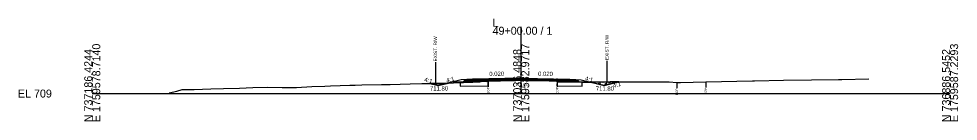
# Model space of a CAD drawing. Extents: x -26 to 4303, y -10 to 9577.
# Drawn here: x 2974.3 to 3302.8, y 8990.3 to 9026.2 of the extents above; entities that cross this region are included whole.
import ezdxf

# ---------------------------------------------------------------- set-up
doc = ezdxf.new("R2010")
doc.units = 0
for name, color, linetype in [('Default', 7, 'Continuous'), ('Exist CMT Pavement', 7, 'Continuous'), ('Old_Level_2', 7, 'Continuous'), ('Pattern 3', 7, 'Continuous'), ('Prop CMT Conc Surface', 7, 'Continuous'), ('Prop CMT Concrete Structures', 7, 'Continuous'), ('Prop CMT Pvmt Course 1', 7, 'Continuous'), ('Prop CMT Pvmt Course 1 CG', 7, 'Continuous'), ('Prop CMT Pvmt Course 1 Wedge', 7, 'Continuous'), ('Prop CMT Pvmt Course 2', 7, 'Continuous'), ('Prop CMT Pvmt Course 2 Wedge', 7, 'Continuous'), ('Prop CMT Pvmt Course 3', 7, 'Continuous'), ('Prop CMT Pvmt Surface', 7, 'Continuous'), ('Prop CMT Pvmt Surface Shoulder', 7, 'Continuous'), ('Prop CMT Pvmt Wedge Surface 1', 7, 'Continuous'), ('Prop CMT Pvmt Wedge Surface 2', 7, 'Continuous'), ('Prop CMT Pvmt Wedge Surface 3', 7, 'Continuous'), ('Prop CMT Shld Paved Course 1', 7, 'Continuous'), ('Prop CMT Shld Paved Course 2', 7, 'Continuous'), ('Prop CMT Shld Paved Course 3', 7, 'Continuous'), ('Prop CMT Slope Grass', 7, 'Continuous'), ('Prop CMT Subgrade Earthwork', 7, 'Continuous'), ('Prop Road Sect_ Recs - UC Shallow (Outline)', 7, 'Continuous'), ('Prop Shade Light', 7, 'Continuous'), ('Prop XS DDE Elevations', 7, 'Continuous'), ('Prop XS Ditch Standard Text', 7, 'Continuous'), ('Prop XS Hydro Elevations', 7, 'Continuous'), ('Prop XS SE Text', 7, 'Continuous'), ('Prop XS Side Slope Text', 7, 'Continuous'), ('Prop XS Wedging', 7, 'Continuous'), ('Scratch_Level_2', 7, 'Continuous')]:
    doc.layers.add(name, color=color, linetype=linetype)

msp = doc.modelspace()

# ---------------------------------------------------------------- linework, layer by layer
at = {"layer": 'Exist CMT Pavement'}
for points in [[(3150, 9005.34), (3133, 9005)], [(3150, 9005.34), (3167, 9005)]]:
    msp.add_lwpolyline(points, dxfattribs=at)
at = {"layer": 'Old_Level_2'}
for p, q in [((3150, 9000), (3150, 9023.41)), ((3150, 9000), (3150, 9023.41)), ((3000, 9000), (3150, 9000)), ((3000, 9000), (3150, 9000)), ((3150, 9000), (3300, 9000)), ((3150, 9000), (3300, 9000))]:
    msp.add_line(p, q, dxfattribs=at)
at = {"layer": 'Pattern 3'}
for p, q in [((3118.62, 9003.55), (3118.58, 9003.43)), ((3119.54, 9003.23), (3119.63, 9003.14)), ((3120.15, 9003.4), (3120.05, 9003.04)), ((3120.49, 9002.93), (3120.59, 9002.95)), ((3121.01, 9003.56), (3120.94, 9003.31)), ((3121.45, 9003.56), (3121.54, 9003.47)), ((3121.9, 9003.12), (3121.97, 9003.04)), ((3122.5, 9003.28), (3122.47, 9003.17)), ((3123.42, 9003.64), (3123.35, 9003.39)), ((3123.6, 9003.65), (3123.76, 9003.49)), ((3175.15, 9003.96), (3175.1, 9003.78)), ((3176, 9004.06), (3175.95, 9003.87)), ((3176.52, 9004.06), (3176.55, 9004.03)), ((3176.91, 9003.68), (3177.38, 9003.21)), ((3177.3, 9003.23), (3177.95, 9003.4)), ((3177.51, 9003.84), (3177.34, 9003.22)), ((3178.39, 9004.07), (3178.31, 9003.75)), ((3178.75, 9004.07), (3178.91, 9003.92)), ((3179.1, 9002.96), (3180.31, 9003.28)), ((3179.26, 9003.56), (3179.82, 9003.01)), ((3179.87, 9003.72), (3179.66, 9002.97)), ((3180.22, 9004.08), (3180.24, 9004.08)), ((3180.78, 9004.09), (3180.66, 9003.64)), ((3180.98, 9004.09), (3181.27, 9003.8)), ((3182.58, 9003.96), (3183.09, 9004.1)), ((3183.17, 9004.1), (3183.1, 9003.83)), ((3183.2, 9004.1), (3183.4, 9003.9))]:
    msp.add_line(p, q, dxfattribs=at)
for points in [[(3118.04, 9003.54), (3121, 9002.8), (3124.57, 9003.7), (3124.11, 9003.68), (3121.85, 9003.57)], [(3135.79, 9004.18), (3136.61, 9004.36), (3137.39, 9004.36), (3137.86, 9004.22)], [(3137.9, 9004.23), (3138.46, 9004.36), (3138.45, 9004.24)], [(3162.55, 9004.39), (3162.55, 9004.22), (3170.16, 9004.06)], [(3184.18, 9004.1), (3179, 9002.8), (3174.01, 9004.05), (3181.14, 9004.09), (3181.96, 9004.1)]]:
    msp.add_lwpolyline(points, close=True, dxfattribs=at)
at = {"layer": 'Prop CMT Conc Surface'}
for points in [[(3138.45, 9004.86), (3133, 9004.75)], [(3133, 9004.75), (3133, 9004.54)], [(3133, 9004.54), (3138.45, 9004.65)], [(3138.45, 9004.65), (3138.45, 9004.86)], [(3162.55, 9004.63), (3162.55, 9004.84)], [(3162.55, 9004.84), (3167, 9004.75)], [(3167, 9004.54), (3162.55, 9004.63)], [(3167, 9004.75), (3167, 9004.54)]]:
    msp.add_lwpolyline(points, dxfattribs=at)
at = {"layer": 'Prop CMT Concrete Structures'}
for points in [[(3150, 9005.22), (3138.45, 9004.99)], [(3150, 9005.22), (3162.55, 9004.97)], [(3133, 9004.75), (3133, 9005)], [(3138.45, 9004.86), (3133, 9004.75)], [(3138.45, 9004.99), (3138.45, 9004.86)], [(3162.55, 9004.97), (3162.55, 9004.84)], [(3162.55, 9004.84), (3167, 9004.75)], [(3167, 9004.75), (3167, 9005)]]:
    msp.add_lwpolyline(points, dxfattribs=at)
at = {"layer": 'Prop CMT Pvmt Course 1'}
for points in [[(3138.45, 9004.65), (3133, 9004.54)], [(3133, 9004.54), (3133, 9004.21)], [(3133, 9004.21), (3138.45, 9004.32)], [(3138.45, 9004.32), (3138.45, 9004.65)], [(3162.55, 9004.63), (3167, 9004.54)], [(3162.55, 9004.3), (3162.55, 9004.63)], [(3167, 9004.21), (3162.55, 9004.3)], [(3167, 9004.54), (3167, 9004.21)]]:
    msp.add_lwpolyline(points, dxfattribs=at)
at = {"layer": 'Prop CMT Pvmt Course 1 Wedge'}
for points in [[(3138.45, 9004.65), (3138.66, 9004.66), (3139.05, 9004.67), (3139.08, 9004.67), (3139.28, 9004.67), (3139.53, 9004.67), (3140.23, 9004.69), (3141.26, 9004.71), (3142.73, 9004.74), (3143.69, 9004.76), (3145.23, 9004.79), (3146.12, 9004.81), (3147.73, 9004.84), (3148.16, 9004.85), (3149.92, 9004.88), (3150, 9004.88)], [(3150, 9004.65), (3149.92, 9004.65), (3148.16, 9004.63), (3147.73, 9004.63), (3146.12, 9004.62), (3145.23, 9004.62), (3143.69, 9004.56), (3142.73, 9004.52), (3141.26, 9004.5), (3140.23, 9004.48), (3139.53, 9004.46), (3139.28, 9004.45), (3139.08, 9004.45), (3139.05, 9004.44), (3138.66, 9004.41), (3138.45, 9004.36)], [(3138.45, 9004.36), (3138.45, 9004.65)], [(3150, 9004.88), (3150, 9004.65)], [(3150, 9004.88), (3151.47, 9004.85), (3152.03, 9004.84), (3152.74, 9004.83), (3153.42, 9004.82), (3155.24, 9004.78), (3155.85, 9004.77), (3157.74, 9004.73), (3159.74, 9004.69), (3160.24, 9004.68), (3160.51, 9004.67), (3160.64, 9004.67), (3160.96, 9004.66), (3161.66, 9004.65), (3162.35, 9004.64), (3162.55, 9004.63)], [(3162.55, 9004.39), (3162.35, 9004.4), (3161.66, 9004.44), (3160.96, 9004.47), (3160.64, 9004.48), (3160.51, 9004.48), (3160.24, 9004.5), (3159.74, 9004.51), (3157.74, 9004.53), (3155.85, 9004.59), (3155.24, 9004.61), (3153.42, 9004.61), (3152.74, 9004.61), (3152.03, 9004.61), (3151.47, 9004.63), (3150, 9004.65)], [(3162.55, 9004.63), (3162.55, 9004.39)]]:
    msp.add_lwpolyline(points, dxfattribs=at)
at = {"layer": 'Prop CMT Pvmt Course 2'}
for points in [[(3133, 9005), (3131, 9004.96), (3130.74, 9004.71)], [(3130.74, 9004.71), (3133, 9004.75)], [(3133, 9004.75), (3133, 9005)], [(3167, 9005), (3169, 9004.96), (3169.26, 9004.71)], [(3167, 9004.75), (3167, 9005)], [(3169.26, 9004.71), (3167, 9004.75)]]:
    msp.add_lwpolyline(points, dxfattribs=at)
at = {"layer": 'Prop CMT Pvmt Course 2 Wedge'}
for points in [[(3131, 9004.96), (3129, 9004.8), (3121, 9002.8), (3118.04, 9003.54)], [(3169, 9004.96), (3171, 9004.8), (3179, 9002.8), (3184.18, 9004.1)]]:
    msp.add_lwpolyline(points, dxfattribs=at)
at = {"layer": 'Prop CMT Pvmt Course 3'}
for points in [[(3133, 9004.75), (3130.74, 9004.71), (3130.53, 9004.49)], [(3130.53, 9004.49), (3133, 9004.54)], [(3133, 9004.54), (3133, 9004.75)], [(3167, 9004.75), (3169.26, 9004.71), (3169.47, 9004.49)], [(3167, 9004.54), (3167, 9004.75)], [(3169.47, 9004.49), (3167, 9004.54)]]:
    msp.add_lwpolyline(points, dxfattribs=at)
at = {"layer": 'Prop CMT Pvmt Surface'}
for points in [[(3150, 9005.09), (3133, 9004.75)], [(3150, 9005.09), (3167, 9004.75)], [(3133, 9004.75), (3133, 9005)], [(3167, 9004.75), (3167, 9005)]]:
    msp.add_lwpolyline(points, dxfattribs=at)
at = {"layer": 'Prop CMT Pvmt Surface Shoulder'}
for points in [[(3138.46, 9004.36), (3138.66, 9004.41), (3139.05, 9004.44), (3139.08, 9004.45), (3139.28, 9004.45), (3139.53, 9004.46), (3140.23, 9004.48), (3141.26, 9004.5), (3142.73, 9004.52), (3143.69, 9004.56), (3145.23, 9004.62), (3146.12, 9004.62), (3147.73, 9004.63), (3148.16, 9004.63), (3149.92, 9004.65), (3150, 9004.65)], [(3150, 9004.65), (3151.47, 9004.63), (3152.03, 9004.61), (3152.74, 9004.61), (3153.42, 9004.61), (3155.24, 9004.61), (3155.85, 9004.59), (3157.74, 9004.53), (3159.74, 9004.51), (3160.24, 9004.5), (3160.51, 9004.48), (3160.64, 9004.48), (3160.96, 9004.47), (3161.66, 9004.44), (3162.35, 9004.4), (3162.55, 9004.39)]]:
    msp.add_lwpolyline(points, dxfattribs=at)
at = {"layer": 'Prop CMT Pvmt Wedge Surface 1'}
for p, q in [((3133.02, 9004.09), (3125.53, 9003.94)), ((3138.45, 9004.19), (3133.02, 9004.09)), ((3162.55, 9004.17), (3166.98, 9004.09)), ((3166.98, 9004.09), (3174.47, 9003.94))]:
    msp.add_line(p, q, dxfattribs=at)
for points in [[(3138.45, 9004.19), (3138.46, 9004.36)], [(3162.55, 9004.17), (3162.55, 9004.39)]]:
    msp.add_lwpolyline(points, dxfattribs=at)
at = {"layer": 'Prop CMT Pvmt Wedge Surface 2'}
for points in [[(3138.45, 9004.99), (3138.66, 9004.99), (3139.05, 9005), (3139.08, 9005), (3139.28, 9005), (3139.53, 9005.01), (3140.23, 9005.02), (3141.26, 9005.04), (3142.73, 9005.07), (3143.69, 9005.09), (3145.23, 9005.12), (3146.12, 9005.14), (3147.73, 9005.17), (3148.16, 9005.18), (3149.92, 9005.22), (3150, 9005.22)], [(3150, 9005.09), (3149.92, 9005.09), (3148.16, 9005.06), (3147.73, 9005.05), (3146.12, 9005.01), (3145.23, 9005), (3143.69, 9004.97), (3142.73, 9004.95), (3141.26, 9004.92), (3140.23, 9004.9), (3139.53, 9004.88), (3139.28, 9004.88), (3139.08, 9004.87), (3139.05, 9004.87), (3138.66, 9004.87), (3138.45, 9004.86)], [(3150, 9005.22), (3150, 9005.09)], [(3150, 9005.22), (3151.47, 9005.19), (3152.03, 9005.18), (3152.74, 9005.16), (3153.42, 9005.15), (3155.24, 9005.11), (3155.85, 9005.1), (3157.74, 9005.06), (3159.74, 9005.02), (3160.24, 9005.01), (3160.51, 9005.01), (3160.64, 9005), (3160.96, 9005), (3161.66, 9004.98), (3162.35, 9004.97), (3162.55, 9004.97)], [(3162.55, 9004.84), (3162.35, 9004.85), (3161.66, 9004.86), (3160.96, 9004.87), (3160.64, 9004.88), (3160.51, 9004.88), (3160.24, 9004.89), (3159.74, 9004.9), (3157.74, 9004.94), (3155.85, 9004.98), (3155.24, 9004.99), (3153.42, 9005.02), (3152.74, 9005.04), (3152.03, 9005.05), (3151.47, 9005.06), (3150, 9005.09)], [(3138.45, 9004.86), (3138.45, 9004.99)], [(3162.55, 9004.97), (3162.55, 9004.84)]]:
    msp.add_lwpolyline(points, dxfattribs=at)
at = {"layer": 'Prop CMT Pvmt Wedge Surface 3'}
for points in [[(3138.45, 9004.86), (3138.66, 9004.87), (3139.05, 9004.87), (3139.08, 9004.87), (3139.28, 9004.88), (3139.53, 9004.88), (3140.23, 9004.9), (3141.26, 9004.92), (3142.73, 9004.95), (3143.69, 9004.97), (3145.23, 9005), (3146.12, 9005.01), (3147.73, 9005.05), (3148.16, 9005.06), (3149.92, 9005.09), (3150, 9005.09)], [(3150, 9005.09), (3150, 9004.88)], [(3150, 9005.09), (3151.47, 9005.06), (3152.03, 9005.05), (3152.74, 9005.04), (3153.42, 9005.02), (3155.24, 9004.99), (3155.85, 9004.98), (3157.74, 9004.94), (3159.74, 9004.9), (3160.24, 9004.89), (3160.51, 9004.88), (3160.64, 9004.88), (3160.96, 9004.87), (3161.66, 9004.86), (3162.35, 9004.85), (3162.55, 9004.84)], [(3150, 9004.88), (3149.92, 9004.88), (3148.16, 9004.85), (3147.73, 9004.84), (3146.12, 9004.81), (3145.23, 9004.79), (3143.69, 9004.76), (3142.73, 9004.74), (3141.26, 9004.71), (3140.23, 9004.69), (3139.53, 9004.67), (3139.28, 9004.67), (3139.08, 9004.67), (3139.05, 9004.67), (3138.66, 9004.66), (3138.45, 9004.65)], [(3138.45, 9004.65), (3138.45, 9004.86)], [(3162.55, 9004.63), (3162.35, 9004.64), (3161.66, 9004.65), (3160.96, 9004.66), (3160.64, 9004.67), (3160.51, 9004.67), (3160.24, 9004.68), (3159.74, 9004.69), (3157.74, 9004.73), (3155.85, 9004.77), (3155.24, 9004.78), (3153.42, 9004.82), (3152.74, 9004.83), (3152.03, 9004.84), (3151.47, 9004.85), (3150, 9004.88)], [(3162.55, 9004.84), (3162.55, 9004.63)]]:
    msp.add_lwpolyline(points, dxfattribs=at)
at = {"layer": 'Prop CMT Shld Paved Course 1'}
for points in [[(3133, 9004.54), (3133, 9005)], [(3150, 9004.88), (3133, 9004.54)], [(3150, 9004.88), (3167, 9004.54)], [(3167, 9004.54), (3167, 9005)]]:
    msp.add_lwpolyline(points, dxfattribs=at)
at = {"layer": 'Prop CMT Shld Paved Course 2'}
for points in [[(3133, 9005), (3131, 9004.96)], [(3167, 9005), (3169, 9004.96)]]:
    msp.add_lwpolyline(points, dxfattribs=at)
at = {"layer": 'Prop CMT Shld Paved Course 3'}
for points in [[(3150, 9005.34), (3133, 9005)], [(3138.45, 9004.99), (3150, 9005.22)], [(3150, 9005.09), (3150, 9005.34)], [(3150, 9005.34), (3167, 9005)], [(3150, 9005.22), (3150, 9005.09), (3150, 9005.09)], [(3162.55, 9004.97), (3150, 9005.22)], [(3133, 9005), (3133, 9004.75)], [(3133, 9004.75), (3138.45, 9004.86)], [(3138.45, 9004.86), (3138.45, 9004.99)], [(3162.55, 9004.84), (3162.55, 9004.97)], [(3167, 9004.75), (3162.55, 9004.84)], [(3167, 9005), (3167, 9004.75)]]:
    msp.add_lwpolyline(points, dxfattribs=at)
at = {"layer": 'Prop CMT Slope Grass'}
msp.add_lwpolyline([(3026.91, 9000.28), (3029.53, 9000.84), (3031.44, 9001.48), (3035.59, 9001.48), (3041.44, 9001.66), (3045.88, 9001.82), (3051.45, 9001.91), (3056.18, 9002.14), (3061.45, 9002.23), (3066.43, 9002.08), (3071.46, 9002.14), (3076.78, 9002.45), (3081.37, 9002.58), (3083.26, 9002.74), (3090.05, 9002.95), (3091.93, 9002.96), (3094.24, 9003.08), (3101.14, 9003.16), (3104.23, 9003.14), (3111.19, 9003.37), (3115.23, 9003.53), (3121.85, 9003.57), (3124.11, 9003.68), (3128.04, 9003.83), (3129.84, 9003.9), (3133.07, 9004.01), (3133.91, 9004.11), (3134.7, 9004.09), (3135.26, 9004.07), (3136.61, 9004.36), (3137.39, 9004.36), (3137.87, 9004.22), (3138.66, 9004.41), (3139.08, 9004.45), (3139.53, 9004.46), (3140.23, 9004.48), (3141.26, 9004.5), (3142.73, 9004.52), (3143.69, 9004.56), (3145.23, 9004.62), (3146.12, 9004.62), (3147.73, 9004.63), (3148.16, 9004.63), (3149.92, 9004.65), (3151.47, 9004.63), (3152.03, 9004.61), (3152.74, 9004.61), (3153.42, 9004.61), (3155.24, 9004.61), (3155.85, 9004.59), (3157.74, 9004.53), (3159.74, 9004.51), (3160.64, 9004.48), (3160.96, 9004.47), (3161.66, 9004.44), (3162.35, 9004.4), (3167.61, 9004.16), (3171.25, 9004.02), (3172.19, 9004.04), (3181.14, 9004.09), (3181.96, 9004.1), (3191.22, 9004.09), (3192, 9004.11), (3192.31, 9004.11), (3193.04, 9004.11), (3201.79, 9004.08), (3204.46, 9003.9), (3205.67, 9003.92), (3214.53, 9004.15), (3230.95, 9004.42), (3231.6, 9004.42), (3241.75, 9004.65), (3251.55, 9004.79), (3261.01, 9004.94), (3261.55, 9004.96), (3262.13, 9004.97), (3271.56, 9005.16)], dxfattribs=at)
at = {"layer": 'Prop CMT Subgrade Earthwork'}
for points in [[(3133, 9004.54), (3130.53, 9004.49), (3130.03, 9004.48), (3129.69, 9004.14)], [(3129.69, 9004.14), (3133, 9004.21)], [(3133, 9004.21), (3133, 9004.54)], [(3167, 9004.54), (3169.47, 9004.49), (3169.97, 9004.48), (3170.31, 9004.14)], [(3167, 9004.21), (3167, 9004.54)], [(3170.31, 9004.14), (3167, 9004.21)]]:
    msp.add_lwpolyline(points, dxfattribs=at)
at = {"layer": 'Prop Road Sect_ Recs - UC Shallow (Outline)'}
for points in [[(3128.72, 9002.54), (3138.48, 9002.74), (3138.45, 9004.24), (3135.79, 9004.18), (3135.26, 9004.07), (3134.7, 9004.09), (3133.91, 9004.11), (3133.07, 9004.01), (3131.4, 9003.95), (3128.7, 9003.86)], [(3162.52, 9002.72), (3171.28, 9002.54), (3171.3, 9004.02), (3171.14, 9004.03), (3170.16, 9004.06), (3168.36, 9004.1), (3162.55, 9004.22)]]:
    msp.add_lwpolyline(points, close=True, dxfattribs=at)
at = {"layer": 'Prop Shade Light'}
for p, q in [((3128.72, 9002.54), (3138.48, 9002.74)), ((3135.79, 9004.18), (3135.26, 9004.07)), ((3138.45, 9004.24), (3138.27, 9004.23)), ((3138.48, 9002.74), (3138.45, 9004.24)), ((3162.55, 9004.22), (3162.52, 9002.72)), ((3162.52, 9002.72), (3171.28, 9002.54)), ((3166.22, 9004.14), (3162.55, 9004.22)), ((3167.62, 9004.11), (3166.22, 9004.14)), ((3166.22, 9004.14), (3166.22, 9004.14)), ((3171.25, 9004.02), (3167.62, 9004.11)), ((3171.3, 9004.02), (3171.25, 9004.02)), ((3171.28, 9002.54), (3171.3, 9004.02))]:
    msp.add_line(p, q, dxfattribs=at)
for points in [[(3135.26, 9004.07), (3134.7, 9004.09), (3133.91, 9004.11), (3133.07, 9004.01), (3129.84, 9003.9), (3128.7, 9003.86), (3128.72, 9002.54)], [(3138.27, 9004.23), (3137.9, 9004.23), (3137.6, 9004.22), (3135.79, 9004.18)]]:
    msp.add_lwpolyline(points, dxfattribs=at)
at = {"layer": 'Prop XS DDE Elevations'}
for points in [[(3121.85, 9003.57), (3124.11, 9003.68), (3124.57, 9003.7), (3121, 9002.8), (3118.04, 9003.54)], [(3133.02, 9004.09), (3125.53, 9003.94), (3124.57, 9003.7), (3128.04, 9003.83), (3129.84, 9003.9), (3133.07, 9004.01), (3133.86, 9004.1)], [(3133.91, 9004.11), (3134.01, 9004.11), (3133.86, 9004.1)], [(3134.01, 9004.11), (3134.7, 9004.09), (3135.26, 9004.07), (3135.57, 9004.14)], [(3136.61, 9004.36), (3137.39, 9004.36), (3137.87, 9004.22), (3138.46, 9004.36), (3138.45, 9004.19), (3135.57, 9004.14)], [(3138.66, 9004.41), (3139.08, 9004.45), (3139.05, 9004.44)], [(3160.24, 9004.5), (3160.37, 9004.49), (3159.74, 9004.51)], [(3160.37, 9004.49), (3160.64, 9004.48), (3160.51, 9004.48)], [(3167.61, 9004.16), (3171.25, 9004.02), (3172.19, 9004.04), (3174.01, 9004.05), (3174.47, 9003.94), (3166.98, 9004.09), (3162.55, 9004.17), (3162.55, 9004.39)], [(3174.01, 9004.05), (3174.47, 9003.94), (3179, 9002.8), (3184.18, 9004.1), (3181.96, 9004.1), (3181.14, 9004.09)]]:
    msp.add_lwpolyline(points, close=True, dxfattribs=at)
at = {"layer": 'Prop XS Ditch Standard Text'}
for p, q in [((3120, 9010.96), (3120, 9003.56)), ((3180, 9011.48), (3180, 9004.08)), ((3138.45, 9004.36), (3138.45, 9002.31)), ((3162.55, 9004.39), (3162.55, 9002.34)), ((3204.46, 9003.9), (3204.46, 9001.85)), ((3214.53, 9004.15), (3214.53, 9002.1))]:
    msp.add_line(p, q, dxfattribs=at)
at = {"layer": 'Prop XS Wedging'}
for p, q in [((3138.45, 9004.36), (3138.45, 9005.27)), ((3138.46, 9004.86), (3150, 9005.09)), ((3150, 9005.09), (3150, 9005.09)), ((3150, 9005.09), (3150, 9005.09)), ((3150, 9005.09), (3162.55, 9004.84)), ((3150, 9005.09), (3150, 9005.09)), ((3162.55, 9004.84), (3150, 9005.09)), ((3162.55, 9004.39), (3162.55, 9005.23)), ((3138.46, 9004.99), (3138.46, 9004.86)), ((3138.46, 9004.86), (3138.46, 9004.36)), ((3138.46, 9004.36), (3138.46, 9004.36)), ((3162.55, 9004.84), (3162.55, 9004.97)), ((3162.55, 9004.39), (3162.55, 9004.84))]:
    msp.add_line(p, q, dxfattribs=at)
for points in [[(3150, 9005.22), (3133, 9004.88)], [(3150, 9005.09), (3133, 9004.75)], [(3150, 9005.22), (3150, 9005.22), (3138.46, 9004.99)], [(3150, 9005.09), (3150, 9005.09), (3138.46, 9004.86)], [(3150, 9005.22), (3167, 9004.88)], [(3162.55, 9004.97), (3150, 9005.22), (3150, 9005.22)], [(3150, 9005.09), (3167, 9004.75)], [(3150, 9005.09), (3150, 9005.09)], [(3150, 9005.09), (3150, 9005.09)], [(3138.46, 9004.36), (3138.66, 9004.41), (3139.08, 9004.45), (3139.53, 9004.46), (3140.23, 9004.48), (3141.26, 9004.5), (3142.73, 9004.52), (3143.69, 9004.56), (3145.23, 9004.62), (3146.12, 9004.62), (3147.73, 9004.63), (3148.16, 9004.63), (3149.92, 9004.65), (3151.47, 9004.63), (3152.03, 9004.61), (3152.74, 9004.61), (3153.42, 9004.61), (3155.24, 9004.61), (3155.85, 9004.59), (3157.74, 9004.53), (3159.74, 9004.51), (3160.64, 9004.48), (3160.96, 9004.47), (3161.66, 9004.44), (3162.35, 9004.4), (3162.55, 9004.39)]]:
    msp.add_lwpolyline(points, dxfattribs=at)
at = {"layer": 'Scratch_Level_2'}
for p, q in [((3162.82, 9004.38), (3162.8, 9004.29)), ((3163.21, 9004.36), (3163.29, 9004.28)), ((3165.18, 9004.27), (3165.17, 9004.25)), ((3165.56, 9004.25), (3165.58, 9004.24))]:
    msp.add_line(p, q, dxfattribs=at)

# ---------------------------------------------------------------- texts
at = {"layer": 'Default'}
msp.add_text('-', height=0.0001, dxfattribs=at).set_placement((3000, 9000))
at = {"layer": 'Old_Level_2'}
for s, p in [('L', (3140, 9023.41)), ('L', (3140, 9023.41)), ('49+00.00 / 1', (3140, 9020.61)), ('49+00.00 / 1', (3140, 9020.61)), ('EL 709', (2974, 8998.6)), ('EL 709', (2974, 8998.6))]:
    msp.add_text(s, height=2.8, dxfattribs=at).set_placement(p)
for s, p in [('N 737186.4244', (3000, 8990)), ('N 737186.4244', (3000, 8990)), ('E 1759578.7140', (3002.8, 8990)), ('E 1759578.7140', (3002.8, 8990)), ('N 737036.4848', (3150, 8990)), ('N 737036.4848', (3150, 8990)), ('E 1759582.9717', (3152.8, 8990)), ('E 1759582.9717', (3152.8, 8990)), ('N 736886.5452', (3300, 8990)), ('N 736886.5452', (3300, 8990)), ('E 1759587.2293', (3302.8, 8990)), ('E 1759587.2293', (3302.8, 8990))]:
    msp.add_text(s, height=2.8, rotation=90, dxfattribs=at).set_placement(p)
at = {"layer": 'Prop CMT Pvmt Course 1 CG'}
msp.add_text('713.65', height=1, dxfattribs=at).set_placement((3147.99, 9002.65))
at = {"layer": 'Prop XS Ditch Standard Text'}
for s, height, p in [('EXIST. R/W', 1.181, (3120.59, 9011.26)), ('EXIST. R/W', 1.181, (3180.59, 9011.78)), ('EOP', 0.787, (3138.85, 8999.91)), ('EOP', 0.787, (3162.94, 8999.95)), ('EOP', 0.787, (3214.93, 8999.7)), ('EOP', 0.787, (3204.85, 8999.45))]:
    msp.add_text(s, height=height, rotation=90, dxfattribs=at).set_placement(p)
at = {"layer": 'Prop XS Hydro Elevations'}
for p in [(3118.11, 9001.06), (3176.11, 9001.02)]:
    msp.add_text('711.80', height=1.5, dxfattribs=at).set_placement(p)
at = {"layer": 'Prop XS SE Text'}
for rotation, p in [(1.1458, (3138.86, 9006.12)), (358.8542, (3155.9, 9006.22))]:
    msp.add_text('0.020', height=1.5, rotation=rotation, dxfattribs=at).set_placement(p)
at = {"layer": 'Prop XS Side Slope Text'}
for rotation, p in [(345.9638, (3116, 9004.26)), (14.0362, (3124, 9003.84)), (345.9638, (3172.2, 9004.69)), (14.0362, (3182.27, 9002.02))]:
    msp.add_text('4:1', height=1.5, rotation=rotation, dxfattribs=at).set_placement(p)

doc.saveas('drawing.dxf')
